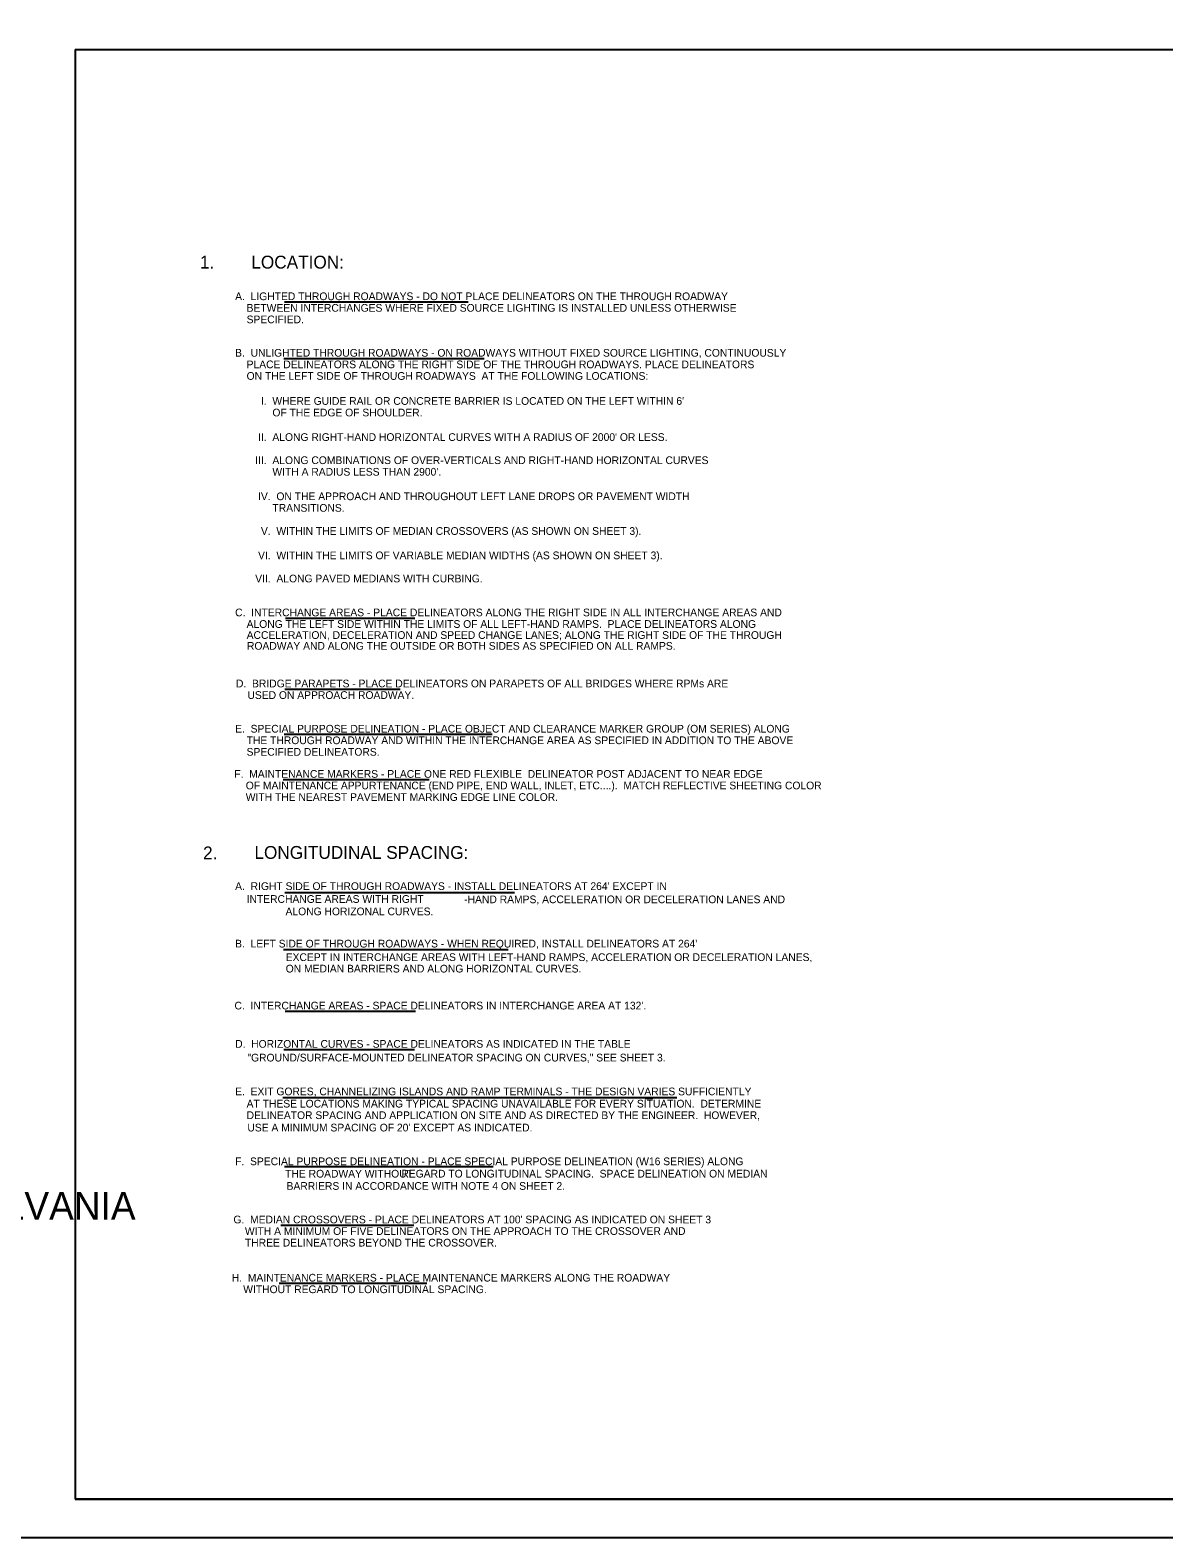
# Model space of a CAD drawing. Extents: x 640253 to 641999, y 298458 to 299646.
# Drawn here: x 641117 to 641558, y 298458 to 299044 of the extents above; entities that cross this region are included whole.
import ezdxf

# ---------------------------------------------------------------- set-up
doc = ezdxf.new("R2010")
doc.units = 0
for name, color, linetype in [('1', 7, 'Continuous'), ('2', 7, 'Continuous'), ('PLT-BNDY', 7, 'Continuous')]:
    doc.layers.add(name, color=color, linetype=linetype)

msp = doc.modelspace()

# ---------------------------------------------------------------- linework, layer by layer
at = {"layer": '1'}
for p, q in [((641134.31, 299036.63), (641920.31, 299036.63)), ((641134.31, 299036.63), (641134.31, 298472.63)), ((641920.31, 298472.63), (641134.31, 298472.63)), ((641134.31, 298472.63), (641720.31, 298472.63))]:
    msp.add_line(p, q, dxfattribs=at)
at = {"layer": '2'}
for p, q in [((641215.86, 298938.4), (641287.29, 298938.4)), ((641215.59, 298916.38), (641293.48, 298916.38)), ((641216.22, 298815.45), (641266.53, 298815.45)), ((641215.94, 298787.77), (641260.85, 298787.77)), ((641215.66, 298770.23), (641296.59, 298770.23)), ((641215.34, 298752.64), (641272.11, 298752.64)), ((641215.94, 298708.72), (641305.27, 298708.72)), ((641215.35, 298686.46), (641302.82, 298686.46)), ((641216.06, 298662.47), (641266.77, 298662.47)), ((641215.59, 298647.58), (641266.43, 298647.58)), ((641215.12, 298628.91), (641368.45, 298628.91)), ((641356.14, 298628.66), (641359.14, 298628.66)), ((641215.84, 298602.03), (641296.99, 298602.03)), ((641214.39, 298579.32), (641266.14, 298579.32)), ((641213.74, 298556.68), (641271.21, 298556.68))]:
    msp.add_line(p, q, dxfattribs=at)
at = {"layer": 'PLT-BNDY'}
msp.add_lwpolyline([(641094.31, 299051.63), (641935.31, 299051.63), (641935.31, 298457.63), (641094.31, 298457.63)], close=True, dxfattribs=at)

# ---------------------------------------------------------------- texts
at = {"layer": '1'}
msp.add_text('COMMONWEALTH OF PENNSYLVANIA', height=10.7828, dxfattribs=at).set_placement((640891.9, 298581.36))
at = {"layer": '2'}
for s, height, p in [('1.', 5, (641182.91, 298951.39)), ('LOCATION:', 5, (641202.89, 298951.39)), ('    A.  LIGHTED THROUGH ROADWAYS - DO NOT PLACE DELINEATORS ON THE THROUGH ROADWAY', 3, (641192.14, 298939.1)), ('        BETWEEN INTERCHANGES WHERE FIXED SOURCE LIGHTING IS INSTALLED UNLESS OTHERWISE', 3, (641192.14, 298934.6)), ('        SPECIFIED.', 3, (641192.14, 298930.1)), ('    B.  UNLIGHTED THROUGH ROADWAYS - ON ROADWAYS WITHOUT FIXED SOURCE LIGHTING, CONTINUOUSLY', 3, (641192.14, 298917.11)), ('        PLACE DELINEATORS ALONG THE RIGHT SIDE OF THE THROUGH ROADWAYS. PLACE DELINEATORS', 3, (641192.14, 298912.61)), ('        ON THE LEFT SIDE OF THROUGH ROADWAYS  AT THE FOLLOWING LOCATIONS:', 3, (641192.14, 298908.11)), ("             I.  WHERE GUIDE RAIL OR CONCRETE BARRIER IS LOCATED ON THE LEFT WITHIN 6'", 3, (641192.14, 298898.38)), ('                 OF THE EDGE OF SHOULDER.', 3, (641192.14, 298893.88)), ("            II.  ALONG RIGHT-HAND HORIZONTAL CURVES WITH A RADIUS OF 2000' OR LESS.", 3, (641192.14, 298884.33)), ('           III.  ALONG COMBINATIONS OF OVER-VERTICALS AND RIGHT-HAND HORIZONTAL CURVES  ', 3, (641192.14, 298875.33)), ("                 WITH A RADIUS LESS THAN 2900'.", 3, (641192.14, 298870.83)), ('            IV.  ON THE APPROACH AND THROUGHOUT LEFT LANE DROPS OR PAVEMENT WIDTH', 3, (641192.14, 298861.29)), ('                 TRANSITIONS.', 3, (641192.14, 298856.79)), ('             V.  WITHIN THE LIMITS OF MEDIAN CROSSOVERS (AS SHOWN ON SHEET 3).', 3, (641192.14, 298847.79)), ('            VI.  WITHIN THE LIMITS OF VARIABLE MEDIAN WIDTHS (AS SHOWN ON SHEET 3).', 3, (641192.14, 298838.31)), ('           VII.  ALONG PAVED MEDIANS WITH CURBING. ', 3, (641192.14, 298829.31)), ('    C.  INTERCHANGE AREAS - PLACE DELINEATORS ALONG THE RIGHT SIDE IN ALL INTERCHANGE AREAS AND', 3, (641192.14, 298816.11)), ('        ALONG THE LEFT SIDE WITHIN THE LIMITS OF ALL LEFT-HAND RAMPS.  PLACE DELINEATORS ALONG ', 3, (641192.14, 298811.61)), ('        ACCELERATION, DECELERATION AND SPEED CHANGE LANES; ALONG THE RIGHT SIDE OF THE THROUGH', 3, (641192.16, 298807.32)), ('        ROADWAY AND ALONG THE OUTSIDE OR BOTH SIDES AS SPECIFIED ON ALL RAMPS.', 3, (641192.28, 298803.11)), ('    D.  BRIDGE PARAPETS - PLACE DELINEATORS ON PARAPETS OF ALL BRIDGES WHERE RPMs ARE', 3, (641192.46, 298788.47)), ('        USED ON APPROACH ROADWAY.', 3, (641192.46, 298783.97)), ('    E.  SPECIAL PURPOSE DELINEATION - PLACE OBJECT AND CLEARANCE MARKER GROUP (OM SERIES) ALONG', 3, (641192.14, 298770.88)), ('        THE THROUGH ROADWAY AND WITHIN THE INTERCHANGE AREA AS SPECIFIED IN ADDITION TO THE ABOVE', 3, (641192.14, 298766.38)), ('        SPECIFIED DELINEATORS.', 3, (641192.14, 298761.88)), ('    F.  MAINTENANCE MARKERS - PLACE ONE RED FLEXIBLE  DELINEATOR POST ADJACENT TO NEAR EDGE', 3, (641191.81, 298753.3)), ('        OF MAINTENANCE APPURTENANCE (END PIPE, END WALL, INLET, ETC....).  MATCH REFLECTIVE SHEETING COLOR ', 3, (641191.81, 298748.8)), ('        WITH THE NEAREST PAVEMENT MARKING EDGE LINE COLOR.  ', 3, (641191.81, 298744.3)), ('2.', 5, (641184.12, 298721.57)), ('LONGITUDINAL SPACING:', 5, (641204.1, 298721.75)), ("    A.  RIGHT SIDE OF THROUGH ROADWAYS - INSTALL DELINEATORS AT 264' EXCEPT IN ", 3, (641192.14, 298709.64)), ('        INTERCHANGE AREAS WITH RIGHT', 3, (641192.14, 298704.64)), ('        -HAND RAMPS, ACCELERATION OR DECELERATION LANES AND', 3, (641276.77, 298704.5)), ('ALONG HORIZONAL CURVES.', 3, (641216.2, 298699.81)), ("    B.  LEFT SIDE OF THROUGH ROADWAYS - WHEN REQUIRED, INSTALL DELINEATORS AT 264' ", 3, (641192.14, 298687.28)), ('EXCEPT IN INTERCHANGE AREAS WITH LEFT-HAND RAMPS, ACCELERATION OR DECELERATION LANES,', 3, (641216.27, 298682.01)), ('ON MEDIAN BARRIERS AND ALONG HORIZONTAL CURVES.', 3, (641216.27, 298677.55)), ("    C.  INTERCHANGE AREAS - SPACE DELINEATORS IN INTERCHANGE AREA AT 132'.", 3, (641191.88, 298663.18)), ('    D.  HORIZONTAL CURVES - SPACE DELINEATORS AS INDICATED IN THE TABLE', 3, (641192.14, 298648.28)), ('       "GROUND/SURFACE-MOUNTED DELINEATOR SPACING ON CURVES," SEE SHEET 3.', 3, (641193.56, 298642.94)), ('    E.  EXIT GORES, CHANNELIZING ISLANDS AND RAMP TERMINALS - THE DESIGN VARIES SUFFICIENTLY', 3, (641192.14, 298629.78)), ('        AT THESE LOCATIONS MAKING TYPICAL SPACING UNAVAILABLE FOR EVERY SITUATION.  DETERMINE ', 3, (641192.14, 298625.03)), ('        DELINEATOR SPACING AND APPLICATION ON SITE AND AS DIRECTED BY THE ENGINEER.  HOWEVER,  ', 3, (641192.14, 298620.53)), ("        USE A MINIMUM SPACING OF 20' EXCEPT AS INDICATED.", 3, (641192.44, 298615.72)), ('    F.  SPECIAL PURPOSE DELINEATION - PLACE SPECIAL PURPOSE DELINEATION (W16 SERIES) ALONG', 3, (641192.14, 298602.59)), ('THE ROADWAY WITHOUT', 3, (641216.05, 298597.78)), ('        REGARD TO LONGITUDINAL SPACING.  SPACE DELINEATION ON MEDIAN', 3, (641252.34, 298597.79)), ('BARRIERS IN ACCORDANCE WITH NOTE 4 ON SHEET 2.', 3, (641216.6, 298593.01)), ("    G.  MEDIAN CROSSOVERS - PLACE DELINEATORS AT 100' SPACING AS INDICATED ON SHEET 3 ", 3, (641191.48, 298579.96)), ('        WITH A MINIMUM OF FIVE DELINEATORS ON THE APPROACH TO THE CROSSOVER AND ', 3, (641191.48, 298575.46)), ('        THREE DELINEATORS BEYOND THE CROSSOVER. ', 3, (641191.48, 298570.96)), ('    H.  MAINTENANCE MARKERS - PLACE MAINTENANCE MARKERS ALONG THE ROADWAY', 3, (641190.83, 298557.32)), ('        WITHOUT REGARD TO LONGITUDINAL SPACING.', 3, (641190.83, 298552.82))]:
    msp.add_text(s, height=height, dxfattribs=at).set_placement(p)

doc.saveas('drawing.dxf')
